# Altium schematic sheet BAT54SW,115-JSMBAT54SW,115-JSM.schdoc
size 127 x 101 mm
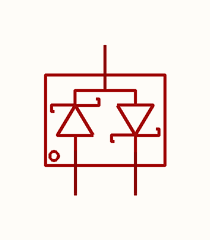
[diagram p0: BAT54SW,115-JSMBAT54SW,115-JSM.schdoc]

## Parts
D?  bat54sw,115-jsm  [SOT-323-3_L2.0-W1.3-P1.30-LS2.3-BR]  (value not drawn)

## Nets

Not connected (* = marked no-connect by the designer): D? 1 2 3

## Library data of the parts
D? = bat54sw,115-jsm: 二极管配置:1个独立式;正向压降(Vf):1V@100mA;直流反向耐压(Vr):30V;整流电流:200mA;; Manufacturer: JSMSEMI(杰盛微); AddInBom: yes; ModelId: 79e13e6d92094c298870c4de3aae48a2; ModelTransform: 90.551,78.74,0,0,0,0,0,0,0; Diode Configuration: 1个独立式; Voltage - DC Reverse(Vr): 30V; Current - Rectified: 200mA; Reverse Leakage Current (Ir): 2uA@25V; Non-Repetitive Peak Forward Surge Current: 600mA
